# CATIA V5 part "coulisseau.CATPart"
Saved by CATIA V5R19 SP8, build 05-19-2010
Part number: coulisseau
Bounding box of the stored display mesh (mm): x -22.149 to 27.851, y 137.981 to 356.681, z 2.252 to 169.457
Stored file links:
  G:\EU_thinkMotion\CFAO_2010\MMS_groupe3\MMS_groupe3\A reprendre\amenand\amenand\coulisseau.CATPart
  F:\thinkmotion CFAO v12.1\essuie_glace.CATProduct
  G:\EU_thinkMotion\CFAO_2010\MMS_groupe3\MMS_groupe3\A reprendre\amenand\amenand\squelette_pignon.CATPart
  G:\EU_thinkMotion\CFAO_2010\MMS_groupe3\MMS_groupe3\A reprendre\amenand\amenand\squelette_coulisseau.CATPart
  G:\EU_thinkMotion\CFAO_2010\MMS_groupe3\MMS_groupe3\A reprendre\amenand\amenand\biellette3.CATPart
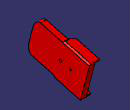
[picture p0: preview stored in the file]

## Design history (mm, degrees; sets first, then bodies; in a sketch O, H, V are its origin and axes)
Set1
  Plane1: linked copy from another document
  Line1: linked copy from another document
  Plane2: linked copy from another document
  Point1: linked copy from another document
  Plane3: linked copy from another document
  Plane4: linked copy from another document
  Point2: linked copy from another document
  Point3: linked copy from another document
Body1 (main body)
  Sketch1 on Plane2, origin (0, 301.9079, -79.6535), H (1, 0, 0), V (0, 0.2551, 0.9669)
    line L1 (27.8512, 209.7086) -> (27.8512, 89.7071)
    point P1 (27.8512, 209.7086)
    line L2 (7.8512, 209.8074) -> (7.8512, 89.806)
    point P3 (7.8512, 209.8074)
    line L3 (27.8512, 209.7086) -> (7.8512, 209.8074)
    point P5 (7.8512, 209.8074)
    point P6 (27.8512, 209.7086)
    line L4 (27.8512, 89.7071) -> (7.8512, 89.806)
    reference projected line E1 (27.8512, 99.7078) -> (27.8512, 199.7078) from Sketch2.L1
    reference projected point E2 (27.8512, 149.7078) from Point1
    reference intersected line E3 through (27.8512, 0) direction (0, 1) from Plane1
    reference intersected line E4 through (7.8512, 0) direction (0, 1) from Plane3
    distance L3 L4 = 120
    distance E2 L4 = 60
    coincidence: P5 L2, P1 P6, P3 P5, L1 E1, L1 E3, L2 E4
    parallelism: L3 L4
  Sketch2 on Plane1, origin (27.8512, 0, 0), H (0, 1, 0), V (0, 0, 1)
    line L1 (355.4053, 123.1158) -> (324.7927, 7.0862)
    point P1 (355.4053, 123.1158)
    point P2 (324.7927, 7.0862)
    reference projected line E1 (340.099, 65.101) -> (155.2727, 113.8645) from Line1
    line L2 (355.4053, 123.1158) -> (181.3608, 169.0346)
    point P3 (355.4053, 123.1158)
    line L3 (324.7927, 7.0862) -> (150.7483, 53.005)
    point P5 (324.7927, 7.0862)
    reference projected line E2 (340.099, 65.101) -> (155.2727, 113.8645) from Line1
    reference projected line E3 (340.099, 65.101) -> (155.2727, 113.8645) from Line1
    reference intersected line E4 through (301.9079, -79.6535) direction (-0.2551, -0.9669) from Plane2
    line L4 (154.3694, 145.1293) -> (139.0632, 87.1145)
    point P7 (154.3694, 145.1293)
    reference projected line E5 (340.099, 65.101) -> (155.2727, 113.8645) from Line1
    connectcurve C1
    connectcurve C2
    distance L2 L3 = 120
    distance E3 L2 = 60
    distance L4 L1 = 200
    length L4 = 60
    distance P7 E5 = 30
    length L2 = 180
    length L3 = 180
    perpendicularity: E1 L1
    parallelism: E2 L2
    coincidence: P3 P1, P2 P5, L1 E4
  SolidCombine1: FirstComponentProfile Sketch1, FirstComponentDirection Sketch1, SecondComponentProfile Sketch2, SecondComponentDirection Sketch2
  Sketch3 on Plane4, origin (27.8512, 195.062, 103.3667), H (1, 0, 0), V (0, 0.2551, 0.9669)
    line L1 (-20, 30) -> (-20, -30)
    arc A1 centre (-20, 0) radius 30 from (-20, 30) to (-20, -30) ccw
    point P3 (-20, 0)
    reference projected point E1 (0, 0) from Point1
    reference intersected line E2 through (-20, 0) direction (0, 1) from Plane3
    radius A1 = 30
    distance P3 E1 = 20
    coincidence: P3 L1, L1 E2
    midpoint: P3 L1
  Pad1: profile Sketch3, direction (0, -0.9669, 0.2551), up to face of SolidCombine1 from Sketch2.L4, opposite side length -20
  Sketch4 on face of SolidCombine1, origin (-2.1172, 146.7224, 116.1449), H (1, 0, 0), V (0, 0.2551, 0.9669)
    point P1 (-0.0316, -0.0238)
    reference projected point E1 (29.9684, -0.0238) from Point1
    reference projected line E2 (9.9684, 29.9762) -> (29.9684, 29.9762) from edge [face of SolidCombine1 | face of SolidCombine1 from Sketch2.C1]
    distance P1 E1 = 30
    distance P1 E2 = 30
  Hole1: placed by Sketch4, at (-2.1488, 146.7163, 116.1219) direction (0, 0.9669, -0.2551), diameter 20, through (limit type 6)
  Sketch5 on Plane2, origin (27.8512, 340.099, 65.101), H (1, 0, 0), V (0, 0.2551, 0.9669)
    line L1 (0, 65) -> (0, 55)
    line L2 (0, 65) -> (-35, 65)
    line L3 (-35, 65) -> (-35, 60)
    line L4 (0, 60) -> (-35, 60)
    point P5 (0, 60)
    reference intersected line E1 through (0, 0) direction (0, 1) from Plane1
    reference intersected line E2 (-20, 60) -> (0, 60) from face of SolidCombine1 from Sketch2.L2
    line L5 (0, -60) -> (-35.0301, -59.8281)
    line L6 (-35.0547, -64.8281) -> (0, -65.0001)
    line L7 (0, -65.0001) -> (0, -60)
    reference intersected line E3 through (0, 0) direction (0, 1) from Plane1
    reference intersected line E4 (-0.0492, -59.9998) -> (-20.0492, -59.9016) from face of SolidCombine1 from Sketch1.L4
    line L8 (-35.0301, -59.8281) -> (-35.0547, -64.8281)
    line L9 (0, 55) -> (0, 60)
    reference intersected line E5 through (0, 0) direction (0, 1) from Plane1
    distance L2 L4 = 5
    distance L1 L3 = 35
    distance L6 L5 = 5
    coincidence: P5 L1, L1 E1, L4 E2, L7 E3, L5 E4, L9 E5
  Pad2: profile Sketch5, direction (0, -0.9669, 0.2551), length 100
  Chamfer1: length 15, angle 45, on edge [face of Pad2 from Sketch5.L8 | end face of Pad2]; edge [face of Pad2 from Sketch5.L3 | end face of Pad2]
  Chamfer2: length 5, angle 45, on edge [face of Pad2 from Sketch5.L2 | end face of Pad2]; edge [face of Pad2 from Sketch5.L6 | end face of Pad2]; edge [face of Pad2 from Sketch5.L2 | face of Pad2]
  Sketch6 on Plane1, origin (27.8512, 317.2987, 86.4108), H (0, 1, 0), V (0, 0, 1)
    point P1 (-65.3347, 1.9432)
    reference projected point E1 (-65.3347, 1.9432) from Point2
    coincidence: P1 E1
  Hole2: placed by Sketch6, at (27.8512, 251.964, 88.354) direction (-1, 0, 0), diameter 10, depth 15
  Sketch7 on Plane1, origin (27.8512, 316.0203, 85.1542), H (0, 1, 0), V (0, 0, 1)
    point P1 (-27.9421, -6.3284)
    reference projected point E1 (-27.9421, -6.3284) from Point3
    coincidence: P1 E1
  Hole3: placed by Sketch7, at (27.8512, 288.0782, 78.8258) direction (-1, 0, 0), diameter 6, through (limit type 6)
